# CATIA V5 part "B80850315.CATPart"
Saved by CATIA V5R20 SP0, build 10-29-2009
Part number: B80850315
Revision: 2
Definition: design
Nomenclature: B80850315
Source: made
Description: NOT SPECIFIED
Bounding box of the stored display mesh (mm): x -27.5 to 27.5, y -27.5 to 27.5, z 0 to 315
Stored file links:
  C:\Users\Raffaele\Desktop\3D X SITO CF\BOLEX\4-PILLAR REF 808\B80850315.CATPart
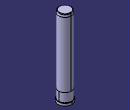
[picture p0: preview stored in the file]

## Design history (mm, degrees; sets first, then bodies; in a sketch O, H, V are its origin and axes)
Body1 "MANIFOLD_SOLID_BREP #450" (main body)
  Solid1: solid without history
